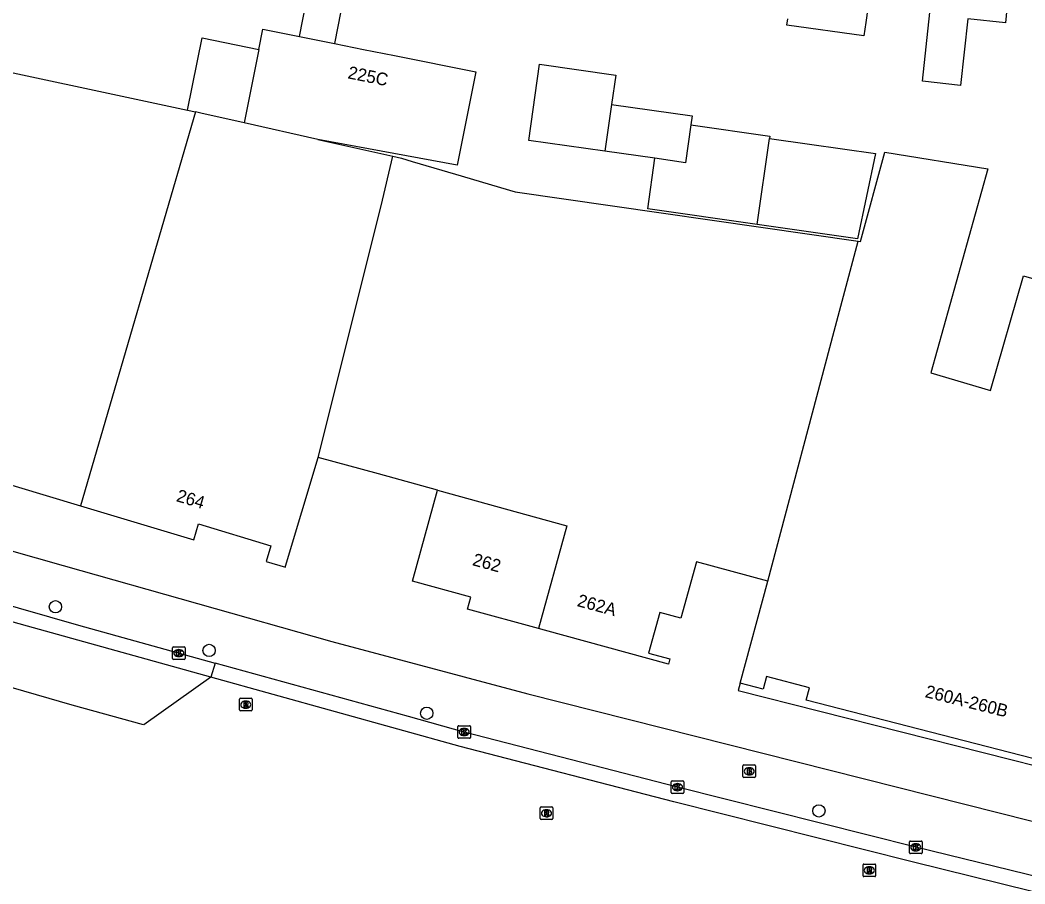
# Model space of a CAD drawing. Extents: x 158087 to 159494, y 382905 to 383981.
# Drawn here: x 158278.9 to 158358.6, y 383090.2 to 383158.7 of the extents above; entities that cross this region are included whole.
import ezdxf

# ---------------------------------------------------------------- set-up
doc = ezdxf.new("R2010")
doc.units = 0
for name, color, linetype in [('IMGEO_Boom', 7, 'Continuous'), ('IMGEO_Brandkraan', 7, 'Continuous'), ('IMGEO_Kolk', 7, 'Continuous'), ('IMGEO_Muur', 7, 'Continuous'), ('IMGEO_Pand', 7, 'Continuous'), ('IMGEO_Pand_nummerreeks', 7, 'Continuous'), ('IMGEO_Pand_overbouw', 7, 'Continuous'), ('IMGEO_Rijbaan_lokaal_gesloten', 7, 'Continuous'), ('IMGEO_Rioolput', 7, 'Continuous'), ('IMGEO_Voetpad_open', 7, 'Continuous')]:
    doc.layers.add(name, color=color, linetype=linetype)

msp = doc.modelspace()

# ---------------------------------------------------------------- linework, layer by layer
at = {"layer": 'IMGEO_Boom'}
for centre in [(158281.733, 383112.178), (158293.919, 383108.711), (158311.181, 383103.726), (158342.29, 383095.977)]:
    msp.add_circle(centre, 0.489, dxfattribs=at)
at = {"layer": 'IMGEO_Brandkraan'}
for p, q in [((158336.263, 383098.697), (158336.263, 383099.549)), ((158336.338, 383099.623), (158337.19, 383099.623)), ((158336.751, 383099.403), (158336.776, 383099.403)), ((158337.264, 383099.549), (158337.264, 383098.697)), ((158337.19, 383098.623), (158336.338, 383098.623)), ((158336.774, 383098.843), (158336.749, 383098.843))]:
    msp.add_line(p, q, dxfattribs=at)
for points in [[(158336.263, 383098.697), (158336.263, 383099.549)], [(158336.338, 383099.623), (158337.19, 383099.623)], [(158336.611, 383099.323), (158336.611, 383098.923), (158336.824, 383098.923)], [(158336.842, 383099.323), (158336.611, 383099.323)], [(158337.264, 383099.549), (158337.264, 383098.697)], [(158337.19, 383098.623), (158336.338, 383098.623)], [(158336.79, 383099.242), (158336.736, 383099.242), (158336.736, 383099.166)], [(158336.736, 383099.166), (158336.789, 383099.166)], [(158336.798, 383099.09), (158336.736, 383099.09), (158336.736, 383099.009)], [(158336.736, 383099.009), (158336.798, 383099.009)]]:
    msp.add_lwpolyline(points, dxfattribs=at)
for centre, radius, start, end in [((158336.34, 383099.547), 0.0765, 91.55205, 178.44795), ((158336.34, 383099.547), 0.0765, 91.55205, 178.44795), ((158336.846, 383099.178), 0.145, 59.4692, 91.53667), ((158336.871, 383099.225), 0.0922, 285.51372, 58.15012), ((158337.188, 383099.547), 0.0765, 1.55205, 88.44795), ((158337.188, 383099.547), 0.0765, 1.55205, 88.44795), ((158336.34, 383098.699), 0.0765, 181.55205, 268.44795), ((158336.34, 383098.699), 0.0765, 181.55205, 268.44795), ((158336.791, 383099.204), 0.0379, 267.82845, 90.93552), ((158336.799, 383099.049), 0.0404, 269.87594, 90.50774), ((158336.83, 383099.174), 0.251, 268.66757, 293.53466), ((158336.876, 383099.033), 0.105, 301.31148, 78.98903), ((158337.188, 383098.699), 0.0765, 271.55205, 358.44795), ((158337.188, 383098.699), 0.0765, 271.55205, 358.44795)]:
    msp.add_arc(centre, radius, start, end, dxfattribs=at)
for centre, major_axis, ratio, start_param, end_param in [((158336.75, 383099.123), (-0.387, 0.002), 0.722429, 4.712389, 7.853982), ((158336.775, 383099.123), (-0.39, 0.002), 0.717154, 1.570796, 4.712389)]:
    msp.add_ellipse(centre, major_axis=major_axis, ratio=ratio, start_param=start_param, end_param=end_param, dxfattribs=at)
at = {"layer": 'IMGEO_Kolk'}
for p, q in [((158291.017, 383108.076), (158291.017, 383108.928)), ((158291.092, 383109.002), (158291.944, 383109.002)), ((158292.018, 383108.928), (158292.018, 383108.076)), ((158291.528, 383108.222), (158291.503, 383108.222)), ((158291.505, 383108.782), (158291.53, 383108.782)), ((158291.944, 383108.002), (158291.092, 383108.002)), ((158313.653, 383101.814), (158313.653, 383102.666)), ((158313.728, 383102.74), (158314.58, 383102.74)), ((158314.141, 383102.52), (158314.166, 383102.52)), ((158314.654, 383102.666), (158314.654, 383101.814)), ((158314.58, 383101.74), (158313.728, 383101.74)), ((158314.164, 383101.96), (158314.139, 383101.96)), ((158330.569, 383097.436), (158330.569, 383098.288)), ((158330.644, 383098.362), (158331.496, 383098.362)), ((158331.057, 383098.142), (158331.082, 383098.142)), ((158331.57, 383098.288), (158331.57, 383097.436)), ((158331.496, 383097.362), (158330.644, 383097.362)), ((158331.08, 383097.582), (158331.055, 383097.582)), ((158349.471, 383092.664), (158349.471, 383093.516)), ((158349.546, 383093.59), (158350.398, 383093.59)), ((158349.959, 383093.37), (158349.984, 383093.37)), ((158350.472, 383093.516), (158350.472, 383092.664)), ((158350.398, 383092.59), (158349.546, 383092.59)), ((158349.982, 383092.81), (158349.957, 383092.81))]:
    msp.add_line(p, q, dxfattribs=at)
for points in [[(158291.017, 383108.076), (158291.017, 383108.928)], [(158291.092, 383109.002), (158291.944, 383109.002)], [(158292.018, 383108.928), (158292.018, 383108.076)], [(158291.338, 383108.702), (158291.461, 383108.702), (158291.461, 383108.551), (158291.591, 383108.702), (158291.755, 383108.702), (158291.609, 383108.551), (158291.762, 383108.302), (158291.61, 383108.302), (158291.525, 383108.466), (158291.461, 383108.399), (158291.461, 383108.302), (158291.338, 383108.302), (158291.338, 383108.702)], [(158291.944, 383108.002), (158291.092, 383108.002)], [(158313.653, 383101.814), (158313.653, 383102.666)], [(158313.728, 383102.74), (158314.58, 383102.74)], [(158314.654, 383102.666), (158314.654, 383101.814)], [(158314.58, 383101.74), (158313.728, 383101.74)], [(158313.974, 383102.44), (158314.097, 383102.44), (158314.097, 383102.289), (158314.227, 383102.44), (158314.391, 383102.44), (158314.245, 383102.289), (158314.398, 383102.04), (158314.246, 383102.04), (158314.161, 383102.204), (158314.097, 383102.137), (158314.097, 383102.04), (158313.974, 383102.04), (158313.974, 383102.44)], [(158330.569, 383097.436), (158330.569, 383098.288)], [(158330.644, 383098.362), (158331.496, 383098.362)], [(158330.89, 383098.062), (158331.013, 383098.062), (158331.013, 383097.911), (158331.143, 383098.062), (158331.307, 383098.062), (158331.161, 383097.911), (158331.314, 383097.662), (158331.162, 383097.662), (158331.077, 383097.826), (158331.013, 383097.759), (158331.013, 383097.662), (158330.89, 383097.662), (158330.89, 383098.062)], [(158331.57, 383098.288), (158331.57, 383097.436)], [(158331.496, 383097.362), (158330.644, 383097.362)], [(158349.471, 383092.664), (158349.471, 383093.516)], [(158349.546, 383093.59), (158350.398, 383093.59)], [(158349.792, 383093.29), (158349.915, 383093.29), (158349.915, 383093.139), (158350.045, 383093.29), (158350.209, 383093.29), (158350.063, 383093.139), (158350.216, 383092.89), (158350.064, 383092.89), (158349.979, 383093.054), (158349.915, 383092.987), (158349.915, 383092.89), (158349.792, 383092.89), (158349.792, 383093.29)], [(158350.472, 383093.516), (158350.472, 383092.664)], [(158350.398, 383092.59), (158349.546, 383092.59)]]:
    msp.add_lwpolyline(points, dxfattribs=at)
for centre, start, end in [((158291.094, 383108.926), 91.55205, 178.44795), ((158291.094, 383108.926), 91.55205, 178.44795), ((158291.942, 383108.926), 1.55205, 88.44795), ((158291.942, 383108.926), 1.55205, 88.44795), ((158291.094, 383108.078), 181.55205, 268.44795), ((158291.094, 383108.078), 181.55205, 268.44795), ((158291.942, 383108.078), 271.55205, 358.44795), ((158291.942, 383108.078), 271.55205, 358.44795), ((158313.73, 383102.664), 91.55205, 178.44795), ((158313.73, 383102.664), 91.55205, 178.44795), ((158314.578, 383102.664), 1.55205, 88.44795), ((158314.578, 383102.664), 1.55205, 88.44795), ((158313.73, 383101.816), 181.55205, 268.44795), ((158313.73, 383101.816), 181.55205, 268.44795), ((158314.578, 383101.816), 271.55205, 358.44795), ((158314.578, 383101.816), 271.55205, 358.44795), ((158330.646, 383098.286), 91.55205, 178.44795), ((158330.646, 383098.286), 91.55205, 178.44795), ((158331.494, 383098.286), 1.55205, 88.44795), ((158331.494, 383098.286), 1.55205, 88.44795), ((158330.646, 383097.438), 181.55205, 268.44795), ((158330.646, 383097.438), 181.55205, 268.44795), ((158331.494, 383097.438), 271.55205, 358.44795), ((158331.494, 383097.438), 271.55205, 358.44795), ((158349.548, 383093.514), 91.55205, 178.44795), ((158349.548, 383093.514), 91.55205, 178.44795), ((158350.396, 383093.514), 1.55205, 88.44795), ((158350.396, 383093.514), 1.55205, 88.44795), ((158349.548, 383092.666), 181.55205, 268.44795), ((158349.548, 383092.666), 181.55205, 268.44795), ((158350.396, 383092.666), 271.55205, 358.44795), ((158350.396, 383092.666), 271.55205, 358.44795)]:
    msp.add_arc(centre, 0.0765, start, end, dxfattribs=at)
for centre, major_axis, ratio, start_param, end_param in [((158291.504, 383108.502), (-0.387, 0.002), 0.722429, 4.712389, 7.853982), ((158291.529, 383108.502), (-0.39, 0.002), 0.717154, 1.570796, 4.712389), ((158314.14, 383102.24), (-0.387, 0.002), 0.722429, 4.712389, 7.853982), ((158314.165, 383102.24), (-0.39, 0.002), 0.717154, 1.570796, 4.712389), ((158331.056, 383097.862), (-0.387, 0.002), 0.722429, 4.712389, 7.853982), ((158331.081, 383097.862), (-0.39, 0.002), 0.717154, 1.570796, 4.712389), ((158349.958, 383093.09), (-0.387, 0.002), 0.722429, 4.712389, 7.853982), ((158349.983, 383093.09), (-0.39, 0.002), 0.717154, 1.570796, 4.712389)]:
    msp.add_ellipse(centre, major_axis=major_axis, ratio=ratio, start_param=start_param, end_param=end_param, dxfattribs=at)
at = {"layer": 'IMGEO_Muur'}
msp.add_lwpolyline([(158303.644, 383109.427), (158319.194, 383105.265)], dxfattribs=at)
at = {"layer": 'IMGEO_Pand'}
for points in [[(158347.41, 383168.443), (158346.706, 383163.493), (158346.002, 383158.541), (158345.85, 383157.475), (158339.757, 383158.341), (158339.828, 383158.838)], [(158357.974, 383167.163), (158357.438, 383162.192), (158357.08, 383158.507), (158354.095, 383158.818), (158353.527, 383153.553), (158350.507, 383153.879), (158351.472, 383162.835), (158352.008, 383167.806)], [(158301.092, 383157.42), (158301.606, 383159.987), (158304.376, 383159.432), (158303.861, 383156.865)], [(158297.853, 383156.407), (158298.171, 383158.005), (158301.092, 383157.42)], [(158292.196, 383151.584), (158293.362, 383157.32), (158297.853, 383156.407)], [(158301.092, 383157.42), (158303.861, 383156.865)], [(158303.861, 383156.865), (158306.179, 383156.4), (158308.629, 383155.909), (158315.091, 383154.614), (158313.609, 383147.219), (158302.551, 383149.261)], [(158297.853, 383156.407), (158296.695, 383150.577)], [(158272.796, 383155.743), (158292.196, 383151.584)], [(158325.321, 383148.326), (158319.272, 383149.185), (158320.131, 383155.224), (158326.179, 383154.364), (158325.849, 383152.041)], [(158325.849, 383152.041), (158325.321, 383148.326)], [(158325.849, 383152.041), (158332.245, 383151.132), (158332.144, 383150.42)], [(158292.83, 383151.446), (158283.733, 383120.195)], [(158292.196, 383151.584), (158292.83, 383151.446)], [(158296.695, 383150.577), (158293.277, 383151.345), (158292.83, 383151.446)], [(158302.551, 383149.261), (158296.695, 383150.577)], [(158332.144, 383150.42), (158331.717, 383147.416), (158329.287, 383147.762)], [(158332.144, 383150.42), (158338.391, 383149.532), (158338.364, 383149.344)], [(158302.551, 383149.261), (158308.489, 383147.926)], [(158338.364, 383149.344), (158341.552, 383148.891), (158346.779, 383148.148), (158345.343, 383141.383), (158337.393, 383142.513)], [(158337.393, 383142.513), (158338.364, 383149.344)], [(158302.582, 383124.02), (158307.558, 383143.998), (158308.489, 383147.926)], [(158308.489, 383147.926), (158309.179, 383147.771), (158310.039, 383147.519), (158313.464, 383146.515), (158318.204, 383145.101), (158345.406, 383141.19)], [(158329.287, 383147.762), (158325.321, 383148.326)], [(158345.406, 383141.19), (158345.597, 383141.163), (158347.51, 383148.249), (158355.692, 383146.915), (158351.159, 383130.728), (158355.895, 383129.333), (158358.526, 383138.435), (158380.047, 383132.214), (158381.972, 383131.774)], [(158337.393, 383142.513), (158328.716, 383143.746), (158329.287, 383147.762)], [(158268.534, 383142.116), (158263.755, 383126.193), (158283.733, 383120.195)], [(158338.235, 383114.205), (158343.493, 383134.04), (158345.406, 383141.19)], [(158283.733, 383120.195), (158292.701, 383117.502), (158293.075, 383118.749), (158298.822, 383117.024), (158298.448, 383115.777), (158299.97, 383115.32), (158299.992, 383115.395), (158302.582, 383124.02)], [(158312.028, 383121.434), (158307.351, 383122.714), (158302.582, 383124.02)], [(158320.048, 383110.442), (158314.411, 383111.986), (158314.675, 383112.951), (158310.052, 383114.217), (158312.028, 383121.434)], [(158312.028, 383121.434), (158322.301, 383118.595), (158320.048, 383110.442)], [(158338.235, 383114.205), (158332.575, 383115.755), (158331.346, 383111.267), (158329.66, 383111.73), (158328.778, 383108.509), (158330.464, 383108.046), (158330.348, 383107.621), (158320.519, 383110.313), (158320.048, 383110.442)], [(158368.275, 383098.017), (158361.001, 383099.683), (158341.29, 383104.763), (158341.545, 383105.75), (158338.127, 383106.632), (158337.872, 383105.644), (158336.032, 383106.118), (158338.235, 383114.205)]]:
    msp.add_lwpolyline(points, dxfattribs=at)
at = {"layer": 'IMGEO_Pand_overbouw'}
msp.add_lwpolyline([(158336.032, 383106.118), (158335.895, 383105.543), (158368.283, 383097.345), (158368.475, 383097.971), (158368.275, 383098.017), (158361.001, 383099.683), (158341.29, 383104.763), (158341.545, 383105.75), (158338.127, 383106.632), (158337.872, 383105.644)], close=True, dxfattribs=at)
at = {"layer": 'IMGEO_Rijbaan_lokaal_gesloten'}
for points in [[(158123.906, 383159.769), (158125.403, 383159.303), (158130.311, 383157.752), (158203.27, 383134.722), (158233.202, 383125.294), (158245.445, 383121.671), (158283.564, 383110.711), (158294.412, 383107.708)], [(158294.047, 383106.593), (158274.356, 383112.076), (158235.952, 383123.218), (158123.545, 383158.624)], [(158288.728, 383102.803), (158283.059, 383104.373), (158260.224, 383110.97), (158260.215, 383110.973)], [(158294.412, 383107.708), (158294.047, 383106.593)], [(158529.869, 383053.842), (158475.26, 383064.998), (158450.798, 383069.996), (158430.763, 383074.2), (158409.761, 383078.872), (158398.798, 383081.361), (158378.836, 383086.042), (158349.972, 383093.09), (158331.07, 383097.862), (158314.154, 383102.24), (158309.729, 383103.467), (158294.412, 383107.708)], [(158294.047, 383106.593), (158288.733, 383102.802)], [(158679.452, 383022.056), (158450.554, 383068.821), (158430.51, 383073.027), (158409.497, 383077.701), (158387.576, 383082.733), (158368.614, 383087.259), (158349.682, 383091.926), (158330.773, 383096.7), (158313.844, 383101.081), (158294.047, 383106.593)]]:
    msp.add_lwpolyline(points, dxfattribs=at)
at = {"layer": 'IMGEO_Rioolput'}
for p, q in [((158296.326, 383103.988), (158296.326, 383104.84)), ((158296.401, 383104.914), (158297.253, 383104.914)), ((158297.327, 383104.84), (158297.327, 383103.988)), ((158296.837, 383104.134), (158296.812, 383104.134)), ((158296.814, 383104.694), (158296.839, 383104.694)), ((158297.253, 383103.914), (158296.401, 383103.914)), ((158320.181, 383095.366), (158320.181, 383096.218)), ((158320.256, 383096.292), (158321.108, 383096.292)), ((158320.669, 383096.072), (158320.694, 383096.072)), ((158321.182, 383096.218), (158321.182, 383095.366)), ((158321.108, 383095.292), (158320.256, 383095.292)), ((158320.692, 383095.512), (158320.667, 383095.512)), ((158345.791, 383090.839), (158345.791, 383091.691)), ((158345.866, 383091.765), (158346.718, 383091.765)), ((158346.279, 383091.545), (158346.304, 383091.545)), ((158346.792, 383091.691), (158346.792, 383090.839)), ((158346.718, 383090.765), (158345.866, 383090.765)), ((158346.302, 383090.985), (158346.277, 383090.985))]:
    msp.add_line(p, q, dxfattribs=at)
for points in [[(158296.326, 383103.988), (158296.326, 383104.84)], [(158296.401, 383104.914), (158297.253, 383104.914)], [(158297.327, 383104.84), (158297.327, 383103.988)], [(158296.915, 383104.612), (158296.663, 383104.614), (158296.663, 383104.214)], [(158296.663, 383104.214), (158296.787, 383104.214), (158296.787, 383104.376), (158296.798, 383104.376)], [(158296.841, 383104.533), (158296.787, 383104.533), (158296.787, 383104.452)], [(158296.787, 383104.452), (158296.839, 383104.452)], [(158296.845, 383104.347), (158296.916, 383104.214), (158297.056, 383104.214), (158296.991, 383104.34)], [(158297.253, 383103.914), (158296.401, 383103.914)], [(158320.181, 383095.366), (158320.181, 383096.218)], [(158320.256, 383096.292), (158321.108, 383096.292)], [(158321.182, 383096.218), (158321.182, 383095.366)], [(158321.108, 383095.292), (158320.256, 383095.292)], [(158320.77, 383095.99), (158320.518, 383095.992), (158320.518, 383095.592)], [(158320.518, 383095.592), (158320.642, 383095.592), (158320.642, 383095.754), (158320.653, 383095.754)], [(158320.696, 383095.911), (158320.642, 383095.911), (158320.642, 383095.83)], [(158320.642, 383095.83), (158320.694, 383095.83)], [(158320.7, 383095.725), (158320.771, 383095.592), (158320.911, 383095.592), (158320.846, 383095.718)], [(158345.791, 383090.839), (158345.791, 383091.691)], [(158345.866, 383091.765), (158346.718, 383091.765)], [(158346.38, 383091.463), (158346.128, 383091.465), (158346.128, 383091.065)], [(158346.306, 383091.384), (158346.252, 383091.384), (158346.252, 383091.303)], [(158346.252, 383091.303), (158346.304, 383091.303)], [(158346.792, 383091.691), (158346.792, 383090.839)], [(158346.718, 383090.765), (158345.866, 383090.765)], [(158346.128, 383091.065), (158346.252, 383091.065), (158346.252, 383091.227), (158346.263, 383091.227)], [(158346.31, 383091.198), (158346.381, 383091.065), (158346.521, 383091.065), (158346.456, 383091.191)]]:
    msp.add_lwpolyline(points, dxfattribs=at)
for centre, radius, start, end in [((158296.403, 383104.838), 0.0765, 91.55205, 178.44795), ((158296.403, 383104.838), 0.0765, 91.55205, 178.44795), ((158297.251, 383104.838), 0.0765, 1.55205, 88.44795), ((158297.251, 383104.838), 0.0765, 1.55205, 88.44795), ((158296.797, 383104.323), 0.0533, 26.02933, 88.69889), ((158296.823, 383104.641), 0.19, 274.7715, 282.96867), ((158296.847, 383104.437), 0.0964, 77.00612, 93.18647), ((158296.861, 383104.494), 0.0378, 276.66336, 79.67722), ((158296.914, 383104.502), 0.109, 350.36119, 89.41601), ((158296.912, 383104.502), 0.112, 277.58423, 350.98172), ((158296.896, 383104.287), 0.108, 29.51342, 73.79051), ((158296.403, 383103.99), 0.0765, 181.55205, 268.44795), ((158296.403, 383103.99), 0.0765, 181.55205, 268.44795), ((158297.251, 383103.99), 0.0765, 271.55205, 358.44795), ((158297.251, 383103.99), 0.0765, 271.55205, 358.44795), ((158320.258, 383096.216), 0.0765, 91.55205, 178.44795), ((158320.258, 383096.216), 0.0765, 91.55205, 178.44795), ((158321.106, 383096.216), 0.0765, 1.55205, 88.44795), ((158321.106, 383096.216), 0.0765, 1.55205, 88.44795), ((158320.258, 383095.368), 0.0765, 181.55205, 268.44795), ((158320.258, 383095.368), 0.0765, 181.55205, 268.44795), ((158320.652, 383095.701), 0.0533, 26.02933, 88.69889), ((158320.678, 383096.019), 0.19, 274.7715, 282.96867), ((158320.702, 383095.815), 0.0964, 77.00612, 93.18647), ((158320.716, 383095.872), 0.0378, 276.66336, 79.67722), ((158320.769, 383095.88), 0.109, 350.36119, 89.41601), ((158320.767, 383095.88), 0.112, 277.58423, 350.98172), ((158320.751, 383095.665), 0.108, 29.51342, 73.79051), ((158321.106, 383095.368), 0.0765, 271.55205, 358.44795), ((158321.106, 383095.368), 0.0765, 271.55205, 358.44795), ((158345.868, 383091.689), 0.0765, 91.55205, 178.44795), ((158345.868, 383091.689), 0.0765, 91.55205, 178.44795), ((158346.288, 383091.492), 0.19, 274.7715, 282.96867), ((158346.312, 383091.288), 0.0964, 77.00612, 93.18647), ((158346.326, 383091.345), 0.0378, 276.66336, 79.67722), ((158346.379, 383091.353), 0.109, 350.36119, 89.41601), ((158346.377, 383091.353), 0.112, 277.58423, 350.98172), ((158346.716, 383091.689), 0.0765, 1.55205, 88.44795), ((158346.716, 383091.689), 0.0765, 1.55205, 88.44795), ((158345.868, 383090.841), 0.0765, 181.55205, 268.44795), ((158345.868, 383090.841), 0.0765, 181.55205, 268.44795), ((158346.262, 383091.174), 0.0533, 26.02933, 88.69889), ((158346.361, 383091.138), 0.108, 29.51342, 73.79051), ((158346.716, 383090.841), 0.0765, 271.55205, 358.44795), ((158346.716, 383090.841), 0.0765, 271.55205, 358.44795)]:
    msp.add_arc(centre, radius, start, end, dxfattribs=at)
for centre, major_axis, ratio, start_param, end_param in [((158296.813, 383104.414), (-0.387, 0.002), 0.722429, 4.712389, 7.853982), ((158296.838, 383104.414), (-0.39, 0.002), 0.717154, 1.570796, 4.712389), ((158320.668, 383095.792), (-0.387, 0.002), 0.722429, 4.712389, 7.853982), ((158320.693, 383095.792), (-0.39, 0.002), 0.717154, 1.570796, 4.712389), ((158346.278, 383091.265), (-0.387, 0.002), 0.722429, 4.712389, 7.853982), ((158346.303, 383091.265), (-0.39, 0.002), 0.717154, 1.570796, 4.712389)]:
    msp.add_ellipse(centre, major_axis=major_axis, ratio=ratio, start_param=start_param, end_param=end_param, dxfattribs=at)
at = {"layer": 'IMGEO_Voetpad_open'}
msp.add_lwpolyline([(158275.706, 383117.342), (158282.349, 383115.44), (158303.644, 383109.427), (158319.194, 383105.265), (158367.165, 383093.156), (158387.943, 383088.186), (158416.661, 383081.611), (158447.771, 383074.9), (158499.365, 383064.353)], dxfattribs=at)

# ---------------------------------------------------------------- texts
at = {"layer": 'IMGEO_Pand_nummerreeks'}
for s, rotation, p in [('225C', 348.66689, (158304.869, 383154.113)), ('264', 343.28682, (158291.256, 383120.568)), ('262', 344.68512, (158314.749, 383115.486)), ('262A', 344.88325, (158323.052, 383112.241)), ('260A-260B', 345.96426, (158350.65, 383105.021))]:
    msp.add_text(s, height=1, rotation=rotation, dxfattribs=at).set_placement(p)

doc.saveas('drawing.dxf')
